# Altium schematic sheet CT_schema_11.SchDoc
size 147 x 119 mm
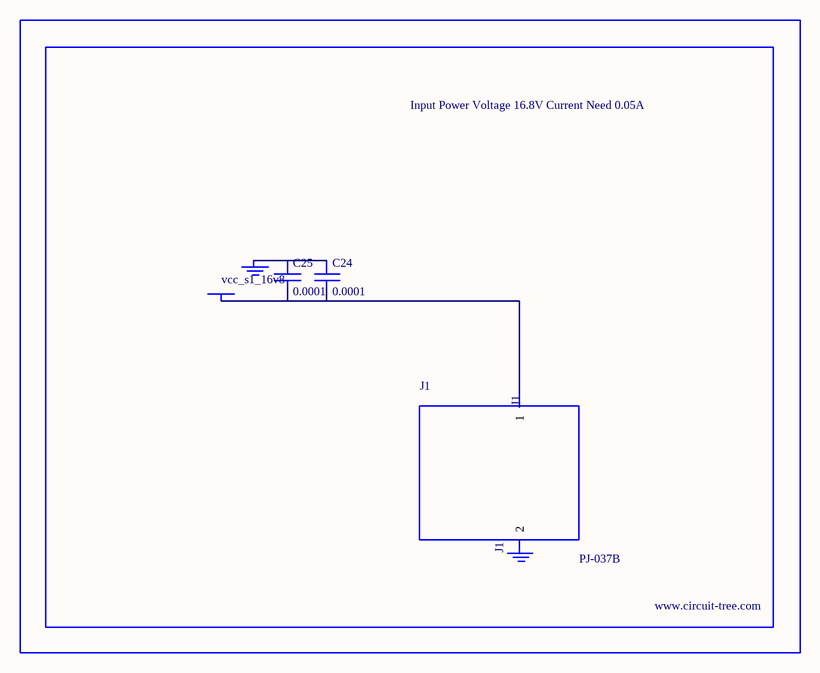
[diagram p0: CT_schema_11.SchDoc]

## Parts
BORDER10  (no value)
C24  0.0001  [EXV-9H]
C25  0.0001  [EXV-9H]
GND_INSTANCE_10_0  (no value)
GND_INSTANCE_10_1  (no value)
J1  PJ-037B  [PJ-037B_PACKAGE]
POWER_INSTANCE_10_0  vcc_s1_16v8

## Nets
NetC24_1: C24.1 C25.1 GND_INSTANCE_10_0.0(GND)
NetC24_2: C24.2 C25.2 J1.1 POWER_INSTANCE_10_0.0(PWR)

Not connected (* = marked no-connect by the designer): GND_INSTANCE_10_1 0(GND); J1 2

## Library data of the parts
BORDER10 = BORDER_PAGE10
C24 C25 = EDK107M035A9HAA
GND_INSTANCE_10_0 GND_INSTANCE_10_1 = GND
POWER_INSTANCE_10_0 = PWR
